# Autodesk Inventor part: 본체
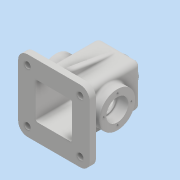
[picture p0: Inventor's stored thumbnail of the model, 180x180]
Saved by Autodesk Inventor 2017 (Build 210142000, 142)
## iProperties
Part Number: 본체
Material: 일반
Document SubType Name: Modeling
Designer: MRC
Density: 1 g/cm^3
Appearance: 기본값
Author: MRC
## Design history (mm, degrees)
sketch "스케치2"
  geometry: L1 (-34, -52.5)-(34, -52.5); L2 (34, -52.5)-(34, 52.5); L3 (34, 52.5)-(-34, 52.5); L4 (-34, 52.5)-(-34, -52.5); L5 (-34, -52.5)-(34, 52.5); L6 (34, -52.5)-(-34, 52.5); 1 further point
  constraints: 12 end point, 2 midpoint, 2 parallel, 1 horizontal, 1 perpendicular
  dimensions: "d0" = 68 distance of L2.end L3.end; "d1" = 105 distance of L1.end L2.end
extrude "돌출1" new body sketch "스케치2" stored distance "d2" = 68; taper "d3" = 0 deg
sketch "스케치4"
  geometry: L1 (68, 0)-(0, 0) reference; L2 (0, 105)-(68, 105) reference; C1 r 28.5 at (34, 52); 2 further points
  constraints: 1 centre point, 1 coincident, 1 midpoint, 1 vertical alignment
  dimensions: "d5" = 57 diameter of C1; "d103" = 52 distance from line of L1 point (34, 52)
extrude "돌출2" join sketch "스케치4" distance "d6" = 15; taper "d7" = 0 deg
sketch "스케치5"
  geometry: L1 (68, 0)-(0, 0) reference; L2 (68, 105)-(0, 105) reference; C1 r 28.5 at (34, 52); 2 further points
  constraints: 1 centre point, 1 coincident, 1 midpoint, 1 vertical alignment
  dimensions: "d8" = 57 diameter of C1; "d104" = 52 distance from line of L1 point (34, 52)
extrude "돌출3" join sketch "스케치5" distance "d9" = 15; taper "d10" = 0 deg
sketch "스케치6"
  geometry: L1 (5, -63)-(63, -63); L2 (63, -63)-(63, -5); L3 (63, -5)-(5, -5); L4 (5, -5)-(5, -63); L5 (5, -63)-(63, -5); L6 (63, -63)-(5, -5); 1 further point
  constraints: 12 end point, 2 midpoint, 2 parallel, 1 horizontal, 1 perpendicular
  dimensions: "d11" = 58 distance of L3.end L2.end; "d12" = 58 distance of L2.end L1.end
extrude "돌출4" cut sketch "스케치6" distance "d13" = 100; taper "d14" = 0 deg
sketch "스케치7"
  geometry: C1 r 28.5 at (0, 0) reference; 2 further points
  constraints: 1 coincident
hole "구멍1" sketch "스케치7" at (0, 0) diameter "d15" = 30; stored, may be unused: countersink angle "d19" = 90 deg, drill point angle "d21" = 0 deg; dims "d16" = 6, "d17" = 35, "d18" = 17, "d20" = 40
sketch "스케치8"
  geometry: C1 r 28.5 at (0, 0) reference; 2 further points
  constraints: 1 vertical alignment
  dimensions: "d105" = 22 distance of C1.centre point (0, 22)
hole "구멍2" sketch "스케치8" diameter "d23" = 3.242; stored, may be unused: countersink angle "d27" = 90 deg, drill point angle "d29" = 118 deg; dims "d24" = 8, "d25" = 35, "d26" = 17, "d28" = 10
sketch "스케치11"
  geometry: L1 (68, -68)-(68, 0) reference; L2 (68, -68)-(0, -68) reference; L3 (0, 0)-(0, -68) reference; L4 (0, 0)-(68, 0) reference; L5 (91, 23)-(91, -91); L6 (91, -91)-(-23, -91); L7 (-23, -91)-(-23, 23); L8 (-23, 23)-(91, 23); 1 further point
  constraints: 8 end point, 3 other
  dimensions: "d33" = 23 distance between parallel lines of L1 L5
extrude "돌출6" join sketch "스케치11" distance "d49" = 10; taper "d50" = 0 deg
sketch "스케치14"
  geometry: 5 further points
  constraints: 2 horizontal alignment, 2 vertical alignment
  dimensions: "d51" = 84 distance of point (-8, -8) point (76, -8); "d52" = 42 horizontal distance of point (34, 34) point (76, -8); "d53" = 42 horizontal distance of point (76, -8) point (34, 34); "d54" = 84 distance of point (76, -8) point (76, 76)
hole "구멍4" sketch "스케치14" at (76, -8), (-8, -8), (-8, 76), (76, 76) diameter "d55" = 10; stored, may be unused: countersink angle "d59" = 90 deg, drill point angle "d61" = 0 deg; dims "d56" = 8, "d57" = 18, "d58" = 2, "d60" = 10
fillet "모깎기2" dims "d62" = 15
node "작업 평면1"
node "작업 평면2"
sketch "스케치18"
  geometry: C1 r 20 at (42, 57); 1 further point
  constraints: 1 centre point, 1 coincident
  dimensions: "d66" = 40 diameter of C1
extrude "돌출7" join sketch "스케치18" distance "d67" = 10; taper "d68" = 0 deg
sketch "스케치19"
  geometry: 1 further point
hole "구멍5" sketch "스케치19" at (0, 0) diameter "d69" = 22.835; stored, may be unused: countersink angle "d73" = 90 deg, drill point angle "d75" = 0 deg; dims "d70" = 40, "d71" = 18, "d72" = 2, "d74" = 40
chamfer "모따기2" distance "d79" = 1; stored, may be unused: second distance "d80" = 2, angle "d81" = 45 deg
sketch "스케치21"
  geometry: L1 (52.5, -34)-(-42.5, -34) reference; L2 (-42.5, -33)-(-42.5, -51) reference; L3 (-42.5, 34)-(52.5, 34) reference; L4 (-42.5, 51)-(-42.5, 33) reference; L5 (42.569, 34)-(-42.5, 49); L6 (-42.5, -42)-(-42.5, -57) reference; L7 (-42.5, 57)-(-52.5, 57) reference; 3 further points
  constraints: 2 end point, 2 point on line
  dimensions: "d82" = 100 deg angle of L5 L4; "d84" = 8 distance from line of L7 L5.end
feature "리브1" sketch "스케치21" dims "d85" = 1, "d86" = 10, "d87" = 0, "d88" = 0, "d89" = 1, "d90" = 1
fillet "모깎기3" dims "d91" = 8
fillet "모깎기4" dims "d92" = 8
fillet "모깎기5" dims "d93" = 3
fillet "모깎기6" dims "d94" = 3
fillet "모깎기7" dims "d95" = 3
fillet "모깎기8" dims "d96" = 3
feature "면 기울기1" dims angle "d97" = 8 deg
sketch "스케치22"
  geometry: L1 (-8, 0)-(-8, -84) reference; L2 (46, 18)-(6, 18) reference; 2 further points
  constraints: 1 other
  dimensions: "d98" = 34 distance from line of L1 point (26, -7); "d99" = 25 distance from line of L2 point (26, -7)
feature "엠보싱1" sketch "스케치22" dims "d100" = 0.5, "d101" = 0
fillet "모깎기9" dims "d102" = 3
node "솔리드1"
mirror "미러2"
pattern_circular "원형 패턴2" dims angle "d107" = 360 deg
mirror "미러3"
mirror "미러4"
other parameters: "d63" = -115, "d65" = -115
